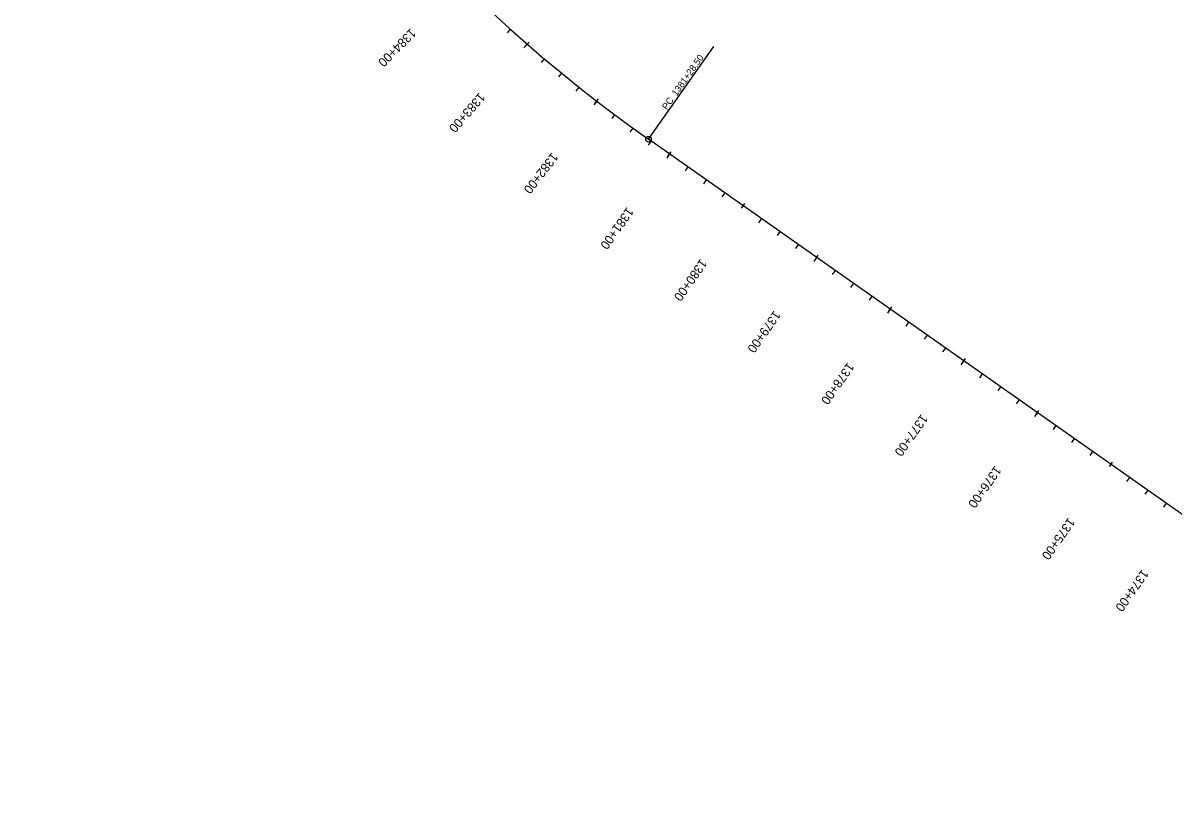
# Model space of a CAD drawing. Extents: x 14541681 to 14544384, y 8572153 to 8583558.
# Drawn here: x 14541811 to 14543091, y 8578459 to 8579336 of the extents above; entities that cross this region are included whole.
import ezdxf

# ---------------------------------------------------------------- set-up
doc = ezdxf.new("R2010")
doc.units = 0
for name, color, linetype in [('Alignment', 7, 'Continuous'), ('TextAlignment', 7, 'Continuous'), ('TextAlignmentLrg', 7, 'Continuous'), ('TextAlignmentSml', 7, 'Continuous')]:
    doc.layers.add(name, color=color, linetype=linetype)

msp = doc.modelspace()

# ---------------------------------------------------------------- linework, layer by layer
at = {"layer": 'Alignment'}
msp.add_line((14543568.7, 8578459.3), (14542506.7, 8579206.3), dxfattribs=at)
msp.add_arc((14543448.6, 8580545.3), 1637.1, 180.077, 234.877, dxfattribs=at)
at = {"layer": 'TextAlignment'}
for p in [(14542506.7, 8579206.3), (14542579.2, 8579309.3)]:
    msp.add_line(p, (14542579.2, 8579309.3), dxfattribs=at)
msp.add_circle((14542506.7, 8579206.3), 3.12, dxfattribs=at)
at = {"layer": 'TextAlignmentLrg'}
for p, q in [((14542371.8, 8579312.1), (14542368.3, 8579308)), ((14542449.1, 8579248.7), (14542445.8, 8579244.4)), ((14542530, 8579189.9), (14542526.9, 8579185.4)), ((14542610, 8579129.8), (14542613.6, 8579134.9)), ((14542693.6, 8579074.8), (14542690.5, 8579070.4)), ((14542775.4, 8579017.3), (14542772.2, 8579012.8)), ((14542857.2, 8578959.8), (14542854, 8578955.3)), ((14542939, 8578902.2), (14542935.8, 8578897.8)), ((14543019, 8578842.2), (14543022.5, 8578847.2))]:
    msp.add_line(p, q, dxfattribs=at)
at = {"layer": 'TextAlignmentSml'}
for p, q in [((14542353.1, 8579328.7), (14542349.5, 8579324.6)), ((14542369.8, 8579309.8), (14542373.9, 8579314.4)), ((14542390.8, 8579295.8), (14542387.3, 8579291.6)), ((14542410, 8579279.8), (14542406.5, 8579275.6)), ((14542429.4, 8579264.1), (14542426.1, 8579259.8)), ((14542447.3, 8579246.3), (14542451, 8579251.1)), ((14542469, 8579233.6), (14542465.8, 8579229.2)), ((14542489.2, 8579218.8), (14542486, 8579214.3)), ((14542509.6, 8579204.3), (14542506.4, 8579199.8)), ((14542528.2, 8579187.4), (14542531.8, 8579192.4)), ((14542550.5, 8579175.5), (14542547.3, 8579171)), ((14542570.9, 8579161.1), (14542567.8, 8579156.7)), ((14542591.4, 8579146.7), (14542588.2, 8579142.3)), ((14542610, 8579129.8), (14542613.6, 8579134.9)), ((14542632.2, 8579118), (14542629.1, 8579113.5)), ((14542652.7, 8579103.6), (14542649.6, 8579099.1)), ((14542673.1, 8579089.2), (14542670, 8579084.7)), ((14542691.8, 8579072.3), (14542695.4, 8579077.3)), ((14542714, 8579060.4), (14542710.9, 8579056)), ((14542734.5, 8579046.1), (14542731.3, 8579041.6)), ((14542754.9, 8579031.7), (14542751.8, 8579027.2)), ((14542773.6, 8579014.8), (14542777.1, 8579019.8)), ((14542795.8, 8579002.9), (14542792.7, 8578998.4)), ((14542816.3, 8578988.5), (14542813.1, 8578984.1)), ((14542836.7, 8578974.1), (14542833.6, 8578969.7)), ((14542855.4, 8578957.2), (14542858.9, 8578962.3)), ((14542877.6, 8578945.4), (14542874.5, 8578940.9)), ((14542898.1, 8578931), (14542894.9, 8578926.5)), ((14542918.5, 8578916.6), (14542915.4, 8578912.1)), ((14542937.2, 8578899.7), (14542940.7, 8578904.7)), ((14542959.4, 8578887.8), (14542956.3, 8578883.4)), ((14542979.9, 8578873.5), (14542976.7, 8578869)), ((14543000.3, 8578859.1), (14542997.2, 8578854.6)), ((14543019, 8578842.2), (14543022.5, 8578847.2)), ((14543041.2, 8578830.3), (14543038.1, 8578825.8)), ((14543061.7, 8578815.9), (14543058.5, 8578811.5)), ((14543082.1, 8578801.5), (14543079, 8578797.1))]:
    msp.add_line(p, q, dxfattribs=at)

# ---------------------------------------------------------------- texts
at = {"layer": 'TextAlignment'}
for s, p in [('1381+28.50', (14542538, 8579253.6)), ('PC', (14542527.2, 8579238.3))]:
    msp.add_text(s, height=7.5, rotation=54.877, dxfattribs=at).set_placement(p)
at = {"layer": 'TextAlignmentLrg'}
for s, p in [('1380+00', (14542564.6, 8579073.9)), ('1375+00', (14542973.5, 8578786.2))]:
    msp.add_text(s, height=10.02, rotation=234.877, dxfattribs=at).set_placement(p)
at = {"layer": 'TextAlignmentSml'}
for s, rotation, p in [('1384+00', 225.3749, (14542242.3, 8579330.3)), ('1383+00', 228.8747, (14542318.7, 8579258.9)), ('1382+00', 232.3745, (14542399.4, 8579192.3)), ('1381+00', 234.877, (14542482.8, 8579131.4)), ('1380+00', 234.877, (14542564.6, 8579073.9)), ('1379+00', 234.877, (14542646.3, 8579016.4)), ('1378+00', 234.877, (14542728.1, 8578958.8)), ('1377+00', 234.877, (14542809.9, 8578901.3)), ('1376+00', 234.877, (14542891.7, 8578843.8)), ('1375+00', 234.877, (14542973.5, 8578786.2)), ('1374+00', 234.877, (14543055.3, 8578728.7))]:
    msp.add_text(s, height=10.02, rotation=rotation, dxfattribs=at).set_placement(p)

doc.saveas('drawing.dxf')
